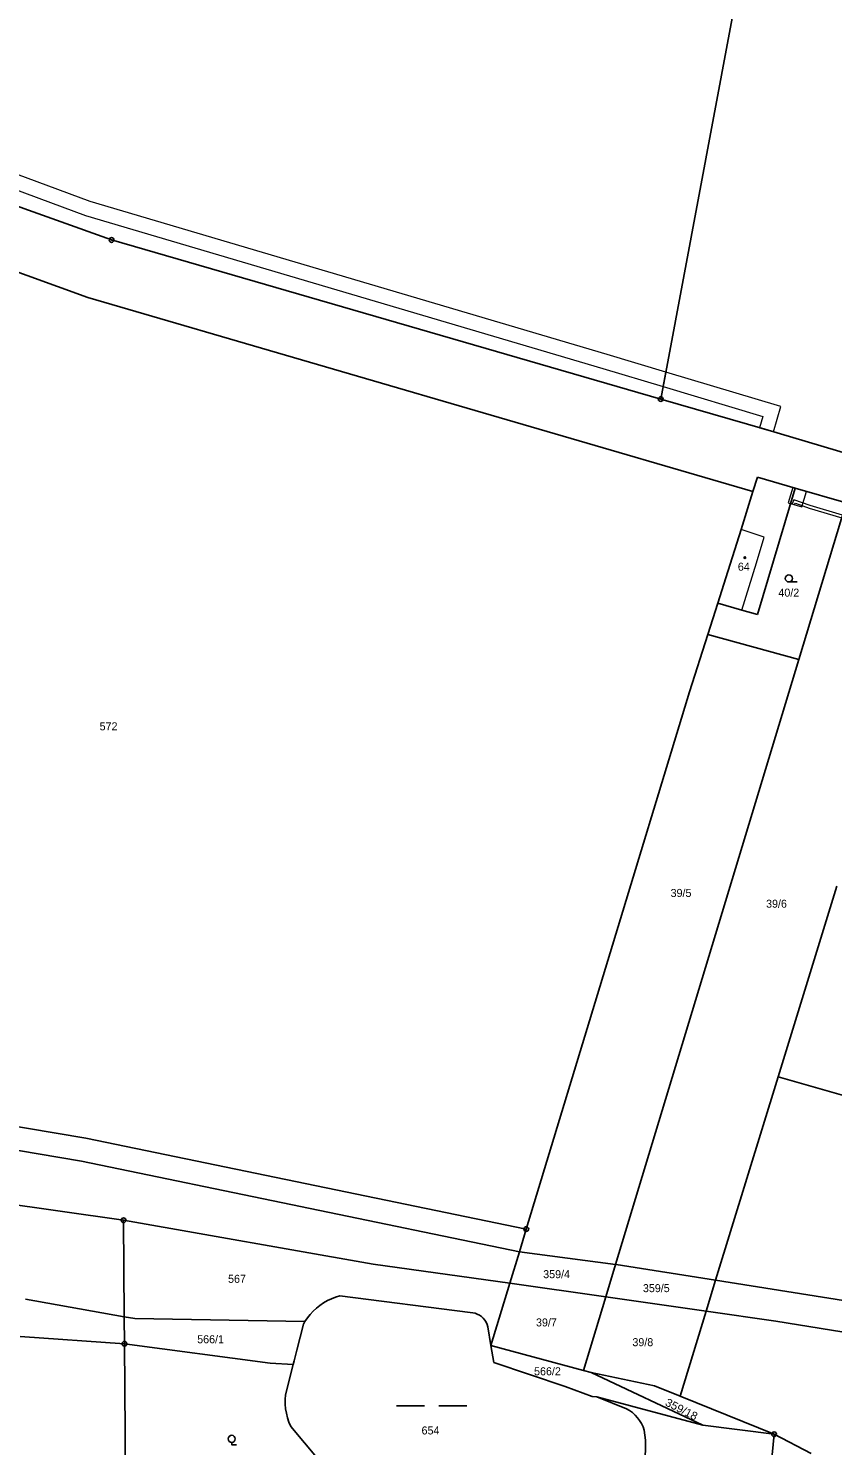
# Model space of a CAD drawing. Extents: x -759947 to -757003, y -1019641 to -1017100.
# Drawn here: x -758266.2 to -758095.4, y -1019052.2 to -1018751.2 of the extents above; entities that cross this region are included whole.
import ezdxf
from ezdxf.enums import TextEntityAlignment as Align

# ---------------------------------------------------------------- set-up
doc = ezdxf.new("R2010")
doc.units = 0
doc.header["$LTSCALE"] = 0.68
for name, color, linetype, lineweight in [('1', 7, 'Continuous', 25), ('13', 7, 'Continuous', 13), ('3', 7, 'Continuous', 25), ('4', 7, 'Continuous', 13), ('5', 7, 'Continuous', 25), ('8', 7, 'Continuous', 25)]:
    doc.layers.add(name, color=color, linetype=linetype, lineweight=lineweight)
doc.layers.add('2', color=7, linetype='Continuous')

msp = doc.modelspace()

# ---------------------------------------------------------------- linework, layer by layer
at = {"layer": '1'}
for p, q in [((-758131.89, -1018829.92), (-758096.23, -1018639.72)), ((-758341.61, -1018762.67), (-758248.48, -1018796.12)), ((-758324.64, -1018782.4), (-758253.56, -1018808.37)), ((-758248.48, -1018796.12), (-758131.89, -1018829.92)), ((-758253.56, -1018808.37), (-758112.31, -1018849.56)), ((-758131.89, -1018829.92), (-758109.76, -1018836.33)), ((-758109.76, -1018836.33), (-758022.67, -1018862.16)), ((-758112.31, -1018849.56), (-758111.31, -1018846.51)), ((-758103.32, -1018848.83), (-758111.31, -1018846.51)), ((-758112.31, -1018849.56), (-758114.83, -1018857.62)), ((-758103.32, -1018848.83), (-758111.35, -1018875.69)), ((-758092.47, -1018851.98), (-758103.32, -1018848.83)), ((-758102.54, -1018885.24), (-758093.48, -1018855.31)), ((-758114.83, -1018857.62), (-758118.08, -1018867.91)), ((-758118.08, -1018867.91), (-758119.76, -1018873.28)), ((-758119.76, -1018873.28), (-758121.88, -1018879.89)), ((-758114.63, -1018874.75), (-758119.76, -1018873.28)), ((-758114.63, -1018874.75), (-758111.35, -1018875.69)), ((-758121.88, -1018879.89), (-758125.79, -1018892.13)), ((-758121.88, -1018879.89), (-758102.54, -1018885.24)), ((-758102.54, -1018885.24), (-758141.47, -1019013.73)), ((-758125.79, -1018892.13), (-758160.42, -1019006.22)), ((-758094.52, -1018933.35), (-758106.97, -1018973.92)), ((-758325.52, -1018974.81), (-758253.97, -1018986.89)), ((-758106.97, -1018973.92), (-758120.22, -1019017.1)), ((-758106.97, -1018973.92), (-758015.69, -1018999.93)), ((-758254.89, -1018991.81), (-758326.63, -1018979.69)), ((-758253.97, -1018986.89), (-758160.42, -1019006.22)), ((-758161.88, -1019011.03), (-758254.89, -1018991.81)), ((-758298.14, -1018996.9), (-758245.93, -1019004.36)), ((-758245.93, -1019004.36), (-758245.79, -1019024.85)), ((-758245.93, -1019004.36), (-758192.94, -1019013.71)), ((-758160.42, -1019006.22), (-758161.88, -1019011.03)), ((-758161.88, -1019011.03), (-758163.91, -1019017.74)), ((-758141.47, -1019013.73), (-758161.88, -1019011.03)), ((-758192.94, -1019013.71), (-758163.91, -1019017.74)), ((-758141.47, -1019013.73), (-758143.57, -1019020.64)), ((-758141.36, -1019013.74), (-758141.47, -1019013.73)), ((-758120.22, -1019017.1), (-758141.36, -1019013.74)), ((-758163.91, -1019017.74), (-758167.92, -1019030.94)), ((-758143.57, -1019020.64), (-758163.91, -1019017.74)), ((-758120.22, -1019017.1), (-758122.24, -1019023.69)), ((-758062.35, -1019026.31), (-758120.22, -1019017.1)), ((-758245.79, -1019024.85), (-758266.77, -1019021.13)), ((-758200, -1019020.41), (-758172.32, -1019023.93)), ((-758143.57, -1019020.64), (-758148.31, -1019036.29)), ((-758122.24, -1019023.69), (-758143.57, -1019020.64)), ((-758122.24, -1019023.69), (-758127.77, -1019041.72)), ((-758107.42, -1019025.81), (-758122.24, -1019023.69)), ((-758245.75, -1019030.6), (-758245.79, -1019024.85)), ((-758243.56, -1019025.24), (-758245.79, -1019024.85)), ((-758243.56, -1019025.24), (-758207.42, -1019025.87)), ((-758209.15, -1019031.97), (-758207.75, -1019026.42)), ((-758207.75, -1019026.42), (-758207.42, -1019025.87)), ((-758168.59, -1019026.97), (-758167.92, -1019030.94)), ((-758059.87, -1019033.48), (-758107.42, -1019025.81)), ((-758267.87, -1019029.06), (-758245.75, -1019030.6)), ((-758245.52, -1019063.39), (-758245.75, -1019030.6)), ((-758245.75, -1019030.6), (-758214.81, -1019034.73)), ((-758209.71, -1019034.19), (-758209.15, -1019031.97)), ((-758167.92, -1019030.94), (-758148.31, -1019036.29)), ((-758167.92, -1019030.94), (-758167.31, -1019034.58)), ((-758214.81, -1019034.73), (-758209.91, -1019034.98)), ((-758209.91, -1019034.98), (-758211.54, -1019041.44)), ((-758209.91, -1019034.98), (-758209.71, -1019034.19)), ((-758167.31, -1019034.58), (-758152.19, -1019039.65)), ((-758148.31, -1019036.29), (-758146.68, -1019036.73)), ((-758146.68, -1019036.73), (-758133.19, -1019039.52)), ((-758146.68, -1019036.73), (-758122.91, -1019047.88)), ((-758133.19, -1019039.52), (-758127.77, -1019041.72)), ((-758152.19, -1019039.65), (-758146.41, -1019041.76)), ((-758146.41, -1019041.76), (-758145.45, -1019041.89)), ((-758145.45, -1019041.89), (-758122.91, -1019047.88)), ((-758145.45, -1019041.89), (-758139.16, -1019044.4)), ((-758127.77, -1019041.72), (-758107.8, -1019049.81)), ((-758195.91, -1019065.47), (-758210.43, -1019048.15)), ((-758122.91, -1019047.88), (-758107.8, -1019049.81)), ((-758107.8, -1019049.81), (-758108.44, -1019056.37)), ((-758099.93, -1019053.87), (-758107.8, -1019049.81))]:
    msp.add_line(p, q, dxfattribs=at)
for points in [[(-758200, -1019020.41), (-758200.903, -1019020.683), (-758201.783, -1019021.023), (-758202.635, -1019021.429), (-758203.453, -1019021.898), (-758204.234, -1019022.428), (-758204.972, -1019023.016), (-758205.663, -1019023.658), (-758206.304, -1019024.35), (-758206.891, -1019025.089), (-758207.42, -1019025.87)], [(-758172.32, -1019023.93), (-758171.808, -1019023.985), (-758171.306, -1019024.105), (-758170.825, -1019024.289), (-758170.37, -1019024.532), (-758169.951, -1019024.831), (-758169.573, -1019025.182), (-758169.243, -1019025.578), (-758168.966, -1019026.013), (-758168.747, -1019026.479), (-758168.59, -1019026.97)], [(-758211.54, -1019041.44), (-758211.616, -1019042.421), (-758211.612, -1019043.406), (-758211.53, -1019044.386), (-758211.369, -1019045.357), (-758211.131, -1019046.312), (-758210.818, -1019047.245), (-758210.43, -1019048.15)], [(-758139.16, -1019044.4), (-758138.505, -1019044.782), (-758137.891, -1019045.227), (-758137.325, -1019045.732), (-758136.812, -1019046.291), (-758136.358, -1019046.899), (-758135.967, -1019047.549), (-758135.643, -1019048.235), (-758135.39, -1019048.95)], [(-758135.39, -1019048.95), (-758135.239, -1019050.009), (-758135.144, -1019051.074), (-758135.105, -1019052.143), (-758135.123, -1019053.212), (-758135.199, -1019054.279), (-758135.33, -1019055.34)]]:
    msp.add_lwpolyline(points, dxfattribs=at)
at = {"layer": '13'}
for points in [[(-758131.39, -1018827.26), (-758130.82, -1018824.19), (-758143.27, -1018820.46), (-758253.04, -1018787.97), (-758291.28, -1018773.78), (-758349.17, -1018751.53), (-758350.08, -1018754.51), (-758292.38, -1018776.68), (-758254.02, -1018790.93), (-758144.15, -1018823.44)], [(-758130.82, -1018824.19), (-758131.39, -1018827.26), (-758110.22, -1018833.61), (-758110.91, -1018836), (-758107.92, -1018836.88), (-758106.38, -1018831.51)], [(-758103.85, -1018848.68), (-758104.81, -1018851.92), (-758101.89, -1018852.82), (-758100.92, -1018849.53)], [(-758100.33, -1018853.07), (-758093.44, -1018855.16), (-758093.25, -1018854.54), (-758093.28, -1018854.59), (-758100.15, -1018852.49), (-758103.61, -1018851.29), (-758104, -1018852.15), (-758103.45, -1018852.39), (-758103.29, -1018852.03)]]:
    msp.add_lwpolyline(points, close=True, dxfattribs=at)
at = {"layer": '3'}
for p, q in [((-758104.673, -1018868.76), (-758102.923, -1018868.76)), ((-758188.019, -1019043.79), (-758182.019, -1019043.79)), ((-758179.019, -1019043.79), (-758173.019, -1019043.79))]:
    msp.add_line(p, q, dxfattribs=at)
msp.add_lwpolyline([(-758222.97, -1019051.542), (-758222.97, -1019052.04), (-758221.969, -1019052.04)], dxfattribs=at)
for centre in [(-758104.6729, -1018868.0098), (-758222.9693, -1019050.7909)]:
    msp.add_circle(centre, 0.75, dxfattribs=at)
at = {"layer": '4'}
for p, q in [((-758109.88, -1018859.24), (-758114.83, -1018857.62)), ((-758111.54, -1018864.67), (-758109.88, -1018859.24)), ((-758114.63, -1018874.75), (-758111.54, -1018864.67))]:
    msp.add_line(p, q, dxfattribs=at)
at = {"layer": '5'}
msp.add_circle((-758114.0168, -1018863.5992), 0.175, dxfattribs=at)
at = {"layer": '8'}
for centre, radius in [((-758248.48, -1018796.1199), 0.5), ((-758248.48, -1018796.1199), 0.0303), ((-758131.89, -1018829.9199), 0.5), ((-758131.89, -1018829.9199), 0.0303), ((-758245.93, -1019004.3599), 0.5), ((-758245.93, -1019004.3599), 0.0303), ((-758160.42, -1019006.2199), 0.5), ((-758160.42, -1019006.2199), 0.0303), ((-758245.75, -1019030.5999), 0.5), ((-758245.75, -1019030.5999), 0.0303), ((-758107.8, -1019049.8099), 0.5), ((-758107.8, -1019049.8099), 0.0303)]:
    msp.add_circle(centre, radius, dxfattribs=at)

# ---------------------------------------------------------------- texts
at = {"layer": '2'}
for s, p in [('64', (-758114.239, -1018866.375)), ('40/2', (-758104.679, -1018871.885)), ('39/5', (-758127.569, -1018935.675)), ('39/6', (-758107.299, -1018937.965)), ('359/4', (-758153.99, -1019016.655)), ('359/5', (-758132.82, -1019019.625)), ('39/7', (-758156.149, -1019026.905)), ('566/1', (-758227.46, -1019030.485)), ('39/8', (-758135.679, -1019031.105)), ('566/2', (-758155.93, -1019037.285)), ('654', (-758180.769, -1019049.855))]:
    msp.add_text(s, height=1.7, dxfattribs=at).set_placement(p, align=Align.CENTER)
for s, p in [('572', (-758251.02, -1018900.275)), ('567', (-758223.75, -1019017.645))]:
    msp.add_text(s, height=1.7, dxfattribs=at).set_placement(p)
at = {"layer": '2', "width": 1.05}
msp.add_text('359/18', height=1.7, rotation=333, dxfattribs=at).set_placement((-758127.8459, -1019045.2678), align=Align.CENTER)

doc.saveas('drawing.dxf')
